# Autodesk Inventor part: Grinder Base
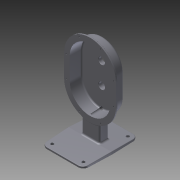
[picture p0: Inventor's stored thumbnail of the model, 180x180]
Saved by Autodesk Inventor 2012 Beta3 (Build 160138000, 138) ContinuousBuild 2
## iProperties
Created: 2010-12
Part Number: Grinder Base
Document SubType Name: Modeling
Designer: Thom Tremblay
Density: 7.25 g/cm^3
Material: Cast Iron
Mass: 1233.53 g
Surface Area: 883.619 cm^2
Volume: 170.142 cm^3
Author: Thom Tremblay
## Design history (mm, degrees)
sketch "Sketch1"
  geometry: L1 (-50, -50)-(-50, 0); L2 (50, 0)-(50, -50); L3 (-60, 0)-(-60, -50); L4 (60, -50)-(60, 0); A1 r 50 centre (0, 0) between (50, 0) and (-50, 0); A2 r 50 centre (0, -50) between (-50, -50) and (50, -50); A3 r 60 centre (0, -50) between (-60, -50) and (60, -50); A4 r 60 centre (0, 0) between (60, 0) and (-60, 0); 1 further point
  constraints: 8 end point, 8 point on circle, 4 centre point, 4 tangent, 2 parallel, 1 coincident, 1 vertical, 3 other
  dimensions: "d0" = 50 distance of L2.start L2.end; "d1" = 50 radius of A1; "d2" = 10 radial gap between concentric circles of A4 A1
extrude "Extrusion1" new body sketch "Sketch1" distance "d3" = 30; taper "d4" = -2 deg
fillet "Fillet1" dims "d7" = 6
shell "Shell3" dims "d132" = 3
extrude "Extrusion2" join sketch "Sketch1" distance "d5" = 4; taper "d6" = -2 deg
fillet "Fillet12" dims "d133" = 2
fillet "Fillet13" dims "d134" = 1
workplane "Work Plane2"
sketch "Sketch7"
  geometry: C1 r 7.5 at (0, -95); 1 further point
  constraints: 1 centre point, 1 vertical alignment
  dimensions: "d64" = 15 diameter of C1; "d65" = 95 distance of point (0, 0) C1.centre
extrude "Extrusion8" join sketch "Sketch7" stored distance "d66" = 12.7; taper "d67" = 2 deg
fillet "Fillet2" dims "d9" = 3, "d10" = 1
hole "Hole3" diameter "d70" = 8; stored, may be unused: countersink angle "d74" = 82 deg, drill point angle "d76" = 118 deg; dims "d68" = 10, "d69" = 10, "d71" = 9, "d72" = 9.525, "d73" = 6.35, "d75" = 30, "d77" = 0.62479, "d78" = 7.985
workplane "Work Plane1"
sketch "Sketch2"
  geometry: L1 (-20.917, -1.5)-(20.917, -1.5); L2 (20.917, -1.5)-(20.219, -21.5); L3 (20.219, -21.5)-(16.219, -21.5); L4 (16.219, -21.5)-(15.695, -6.5); L5 (15.695, -6.5)-(-15.695, -6.5); L6 (-15.695, -6.5)-(-16.219, -21.5); L7 (-16.219, -21.5)-(-20.219, -21.5); L8 (-20.219, -21.5)-(-20.917, -1.5); L9 (-16.219, -21.5)-(16.219, -21.5); 3 further points
  constraints: 18 end point, 3 parallel, 2 equal length, 2 midpoint, 2 vertical alignment, 1 collinear, 1 horizontal
  dimensions: "d12" = 4 deg angle of L8 L6; "d13" = 88 deg angle of L8 L1; "d14" = 1.5 distance from line of point (0, 0) L1; "d15" = 20 vertical distance of L1.end L2.end; "d16" = 4 distance of L2.end L3.end; "d17" = 5 distance between parallel lines of L1 L5
extrude "Extrusion3" join sketch "Sketch2" stored distance "d18" = 27.94; taper "d19" = 0 deg
sketch "Sketch3"
  geometry: L1 (-70, -150)-(70, -150) reference; L2 (-50, -150)-(50, -150); L3 (50, -150)-(50, -144); L4 (50, -144)-(-50, -144); L5 (-50, -144)-(-50, -150); 2 further points
  constraints: 8 end point, 2 parallel, 1 horizontal, 1 midpoint, 1 perpendicular, 1 point on line, 1 vertical alignment
  dimensions: "d20" = 100 distance of L3.end L4.end; "d21" = 6 distance of L2.end L3.end
extrude "Extrusion4" join sketch "Sketch3" distance "d22" = 63.5; taper "d23" = 0 deg
feature "FaceDraft1" dims angle "d24" = 2 deg
sketch "Sketch4"
  geometry: L1 (-50, -150)-(50, -150) reference; L2 (50, -150)-(50, -143.773) reference; L3 (50, -143.773)-(-50, -143.773) reference; L4 (-50, -143.773)-(-50, -150) reference; 1 further point
extrude "Extrusion5" join sketch "Sketch4" distance "d25" = 63.5; taper "d26" = 0 deg
feature "FaceDraft2" dims angle "d27" = 2 deg
fillet "Fillet3" dims "d28" = 12
fillet "Fillet4"
fillet "Fillet5"
fillet "Fillet6" dims "d29" = 4
fillet "Fillet7" dims "d30" = 4
fillet "Fillet8" dims "d31" = 2
sketch "Sketch5"
  geometry: C1 r 12.5 at (0, 0); 1 further point
  constraints: 1 centre point, 1 coincident
  dimensions: "d32" = 25 diameter of C1
extrude "Extrusion6" join sketch "Sketch5" distance "d33" = 5; taper "d35" = -2 deg; dims "d34" = 8, "d36" = -2 deg
hole "Hole1" diameter "d40" = 14; stored, may be unused: countersink angle "d44" = 82 deg, drill point angle "d46" = 118 deg; dims "d38" = 10, "d39" = 10, "d41" = 19.05, "d42" = 9.525, "d43" = 6.35, "d45" = 25.4
sketch "Sketch10"
  geometry: C1 r 12.5 at (0, -50); A1 r 60 centre (0, -50) between (-60, -50) and (-18.704, -107.01) reference; 1 further point
  constraints: 1 centre point, 1 coincident
  dimensions: "d135" = 25 diameter of C1
extrude "Extrusion9" join sketch "Sketch10" distance "d136" = 12; taper "d137" = -2 deg
fillet "Fillet9" dims "d37" = 3
hole "Hole2" diameter "d55" = 14; stored, may be unused: countersink angle "d59" = 82 deg, drill point angle "d61" = 118 deg; dims "d53" = 10, "d54" = 10, "d56" = 19.05, "d57" = 9.525, "d58" = 6.35, "d60" = 8
hole "Hole4" diameter "d81" = 7; stored, may be unused: countersink angle "d85" = 82 deg, drill point angle "d87" = 118 deg; dims "d79" = 10, "d80" = 10, "d82" = 12.7, "d83" = 12.8778, "d84" = 6.35, "d86" = 30.48
hole "Hole5" diameter "d90" = 7; stored, may be unused: countersink angle "d94" = 82 deg, drill point angle "d96" = 118 deg; dims "d88" = 10, "d89" = 10, "d91" = 12.7, "d92" = 12.8778, "d93" = 6.35, "d95" = 30.48
hole "Hole6" diameter "d99" = 7; stored, may be unused: countersink angle "d103" = 82 deg, drill point angle "d105" = 118 deg; dims "d97" = 10, "d98" = 10, "d100" = 12.7, "d101" = 12.8778, "d102" = 6.35, "d104" = 30.48
hole "Hole7" diameter "d108" = 7; stored, may be unused: countersink angle "d112" = 82 deg, drill point angle "d114" = 118 deg; dims "d106" = 10, "d107" = 10, "d109" = 12.7, "d110" = 12.8778, "d111" = 6.35, "d113" = 30.48
fillet "Fillet11" dims "d122" = 1
node "Hole10"
chamfer "Chamfer1" distance "d138" = 1; stored, may be unused: second distance "d139" = 2, angle "d140" = 45 deg
body "Solid1"
node "Projected Loop1"
sketch "Sketch9"
  geometry: 8 further points
hole "Hole9" sketch "Sketch9" diameter "d123" = 3.242; stored, may be unused: countersink angle "d127" = 82 deg, drill point angle "d129" = 0 deg; dims "d124" = 19.05, "d125" = 9.525, "d126" = 6.35, "d128" = 25.4
other parameters: "d63" = -35
